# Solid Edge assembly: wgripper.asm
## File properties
Author: nakano
Template: iso metric assembly.asm
Last saved by: nakano
Revision: 6
Application: Solid Edge
Username: nakano
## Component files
gripper.par
hitec hs-422.asm
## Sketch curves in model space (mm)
line (0, 0, 0) -> (0, 0, 3.8818)
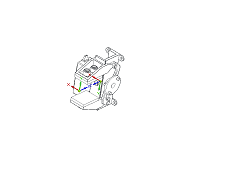
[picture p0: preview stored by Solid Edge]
